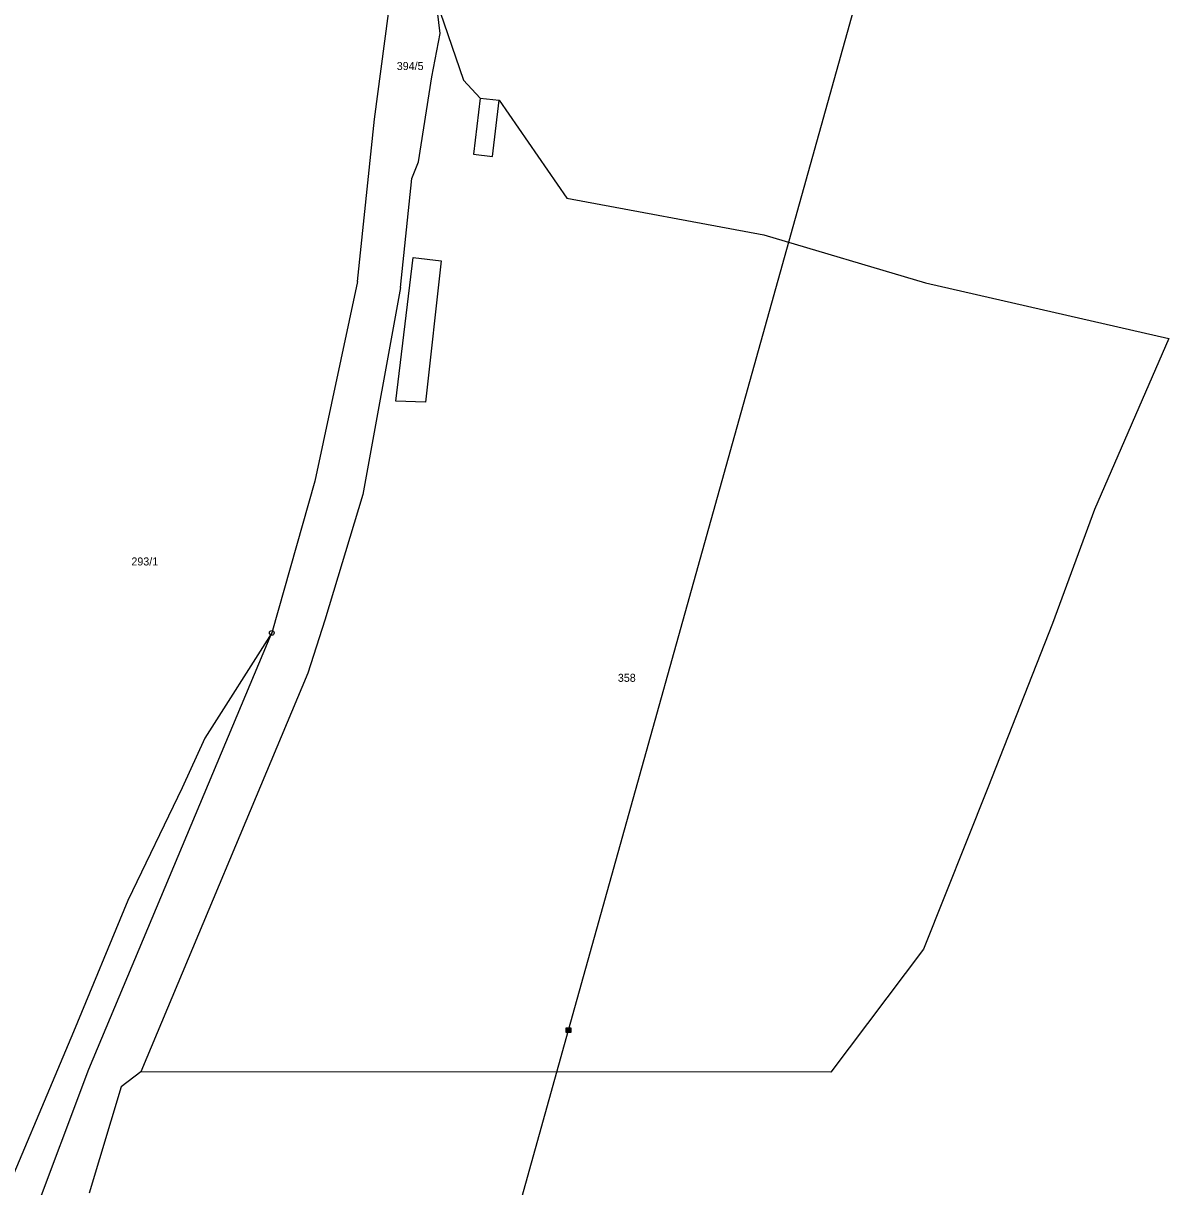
# Model space of a CAD drawing. Extents: x -735249 to -729401, y -1124843 to -1121828.
# Drawn here: x -731391.5 to -731148.2, y -1123208.3 to -1122961.1 of the extents above; entities that cross this region are included whole.
import ezdxf

# ---------------------------------------------------------------- set-up
doc = ezdxf.new("R2010")
doc.units = 0
for name, color, linetype in [('Vrstva 1', 7, 'Continuous'), ('Vrstva 12', 7, 'Continuous'), ('Vrstva 18', 7, 'Continuous'), ('Vrstva 25', 7, 'Continuous'), ('Vrstva 4', 7, 'Continuous')]:
    doc.layers.add(name, color=color, linetype=linetype)

msp = doc.modelspace()

# ---------------------------------------------------------------- linework, layer by layer
at = {"layer": 'Vrstva 1'}
for points in [[(-731316.89, -1122981.45), (-731313.28, -1122954.17)], [(-731303.79, -1122956.27), (-731297.98, -1122973.19)], [(-731302.91, -1122963.25), (-731303.79, -1122956.27)], [(-731304.67, -1122972.5), (-731302.91, -1122963.25)], [(-731307.53, -1122990.53), (-731304.67, -1122972.5)], [(-731297.98, -1122973.19), (-731294.42, -1122976.98)], [(-731294.42, -1122976.98), (-731290.39, -1122977.46)], [(-731290.39, -1122977.46), (-731276.06, -1122998.26)], [(-731320.48, -1123015.95), (-731316.89, -1122981.45)], [(-731308.98, -1122994.11), (-731307.53, -1122990.53)], [(-731311.37, -1123017.22), (-731308.98, -1122994.11)], [(-731276.06, -1122998.26), (-731234.17, -1123006.02)], [(-731234.17, -1123006.02), (-731199.89, -1123016.21)], [(-731320.48, -1123015.95), (-731329.55, -1123058.39)], [(-731311.37, -1123017.22), (-731319.33, -1123061.2)], [(-731199.89, -1123016.21), (-731148.23, -1123028.04)], [(-731148.23, -1123028.04), (-731164.02, -1123064.39)], [(-731329.55, -1123058.39), (-731338.68, -1123090.62)], [(-731319.33, -1123061.2), (-731327.43, -1123087.91)], [(-731164.02, -1123064.39), (-731172.91, -1123088.59)], [(-731327.43, -1123087.91), (-731331.05, -1123099.18)], [(-731172.91, -1123088.59), (-731186.67, -1123123.52)], [(-731377.51, -1123183.28), (-731338.68, -1123090.62)], [(-731338.68, -1123090.62), (-731352.9, -1123113)], [(-731331.05, -1123099.18), (-731366.5, -1123183.9)], [(-731352.9, -1123113), (-731357.73, -1123123.51)], [(-731357.73, -1123123.51), (-731369.27, -1123147.48)], [(-731186.67, -1123123.52), (-731200.31, -1123157.79)], [(-731369.27, -1123147.48), (-731380.77, -1123175.37)], [(-731200.31, -1123157.79), (-731219.97, -1123183.93)], [(-731380.77, -1123175.37), (-731398.66, -1123217.58)], [(-731413.52, -1123278.88), (-731377.51, -1123183.28)], [(-731366.5, -1123183.9), (-731370.67, -1123187.03)], [(-731219.97, -1123183.93), (-731366.5, -1123183.9)], [(-731370.67, -1123187.03), (-731377.49, -1123209.65)]]:
    msp.add_lwpolyline(points, dxfattribs=at)
at = {"layer": 'Vrstva 12'}
for points in [[(-731275.69, -1123175.03), (-731194.02, -1122882.6)], [(-731368.82, -1123509.2), (-731275.69, -1123175.03)]]:
    msp.add_lwpolyline(points, dxfattribs=at)
at = {"layer": 'Vrstva 25'}
for points in [[(-731276.19, -1123174.53), (-731275.19, -1123174.53), (-731275.19, -1123175.53), (-731276.19, -1123175.53), (-731276.19, -1123174.53)], [(-731275.99, -1123174.73), (-731275.39, -1123174.73), (-731275.39, -1123175.33), (-731275.99, -1123175.33), (-731275.99, -1123174.73)], [(-731275.79, -1123174.93), (-731275.59, -1123174.93), (-731275.59, -1123175.13), (-731275.79, -1123175.13), (-731275.79, -1123174.93)]]:
    msp.add_lwpolyline(points, dxfattribs=at)
for radius in [0.5, 0.032]:
    msp.add_circle((-731338.68, -1123090.62), radius, dxfattribs=at)
at = {"layer": 'Vrstva 4'}
for points in [[(-731294.42, -1122976.98), (-731295.82, -1122988.91)], [(-731291.79, -1122989.4), (-731290.39, -1122977.46)], [(-731295.82, -1122988.91), (-731291.79, -1122989.4)], [(-731312.38, -1123041.37), (-731308.64, -1123010.86)], [(-731308.64, -1123010.86), (-731302.69, -1123011.59)], [(-731302.69, -1123011.59), (-731306.08, -1123041.61)], [(-731306.08, -1123041.61), (-731312.38, -1123041.37)]]:
    msp.add_lwpolyline(points, dxfattribs=at)

# ---------------------------------------------------------------- texts
at = {"layer": 'Vrstva 18'}
for s, p in [('394/5', (-731312.15, -1122971.03)), ('293/1', (-731368.5, -1123076.29)), ('358', (-731265.2, -1123101.01))]:
    msp.add_text(s, height=1.7, dxfattribs=at).set_placement(p)

doc.saveas('drawing.dxf')
